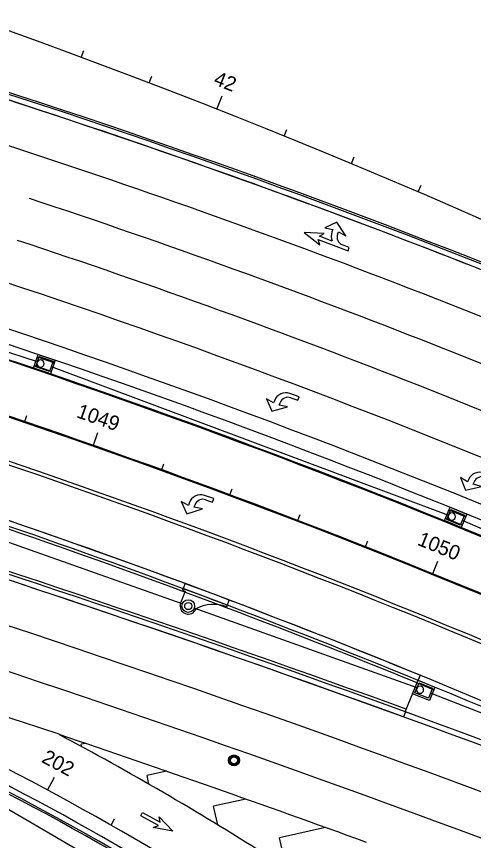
# Model space of a CAD drawing. Extents: x 468143 to 491361, y 1438528 to 1468730.
# Drawn here: x 487216.5 to 487342.4, y 1467246.7 to 1467474 of the extents above; entities that cross this region are included whole.
import ezdxf

# ---------------------------------------------------------------- set-up
doc = ezdxf.new("R2010")
doc.units = 0
doc.layers.add('Default', color=7, linetype='Continuous')
doc.layers.add('Xreference_dp', color=7, linetype='Continuous')

# ---------------------------------------------------------------- blocks, each defined once
blk = doc.blocks.new('POINT_DISPLAY')
at = {"layer": 'Default'}
blk.add_line((0, 0), (0, 0), dxfattribs=at)
blk = doc.blocks.new('InltCurb7_60')
at = {"layer": 'Default'}
for p, q in [((2.5, 4), (-2.5, 4)), ((-2.5, 4), (-2.5, 0)), ((2.5, 0), (2.5, 4)), ((-2.5, 0.75), (2.5, 0.75)), ((-2.5, 0), (2.5, 0))]:
    blk.add_line(p, q, dxfattribs=at)
blk.add_lwpolyline([(-2, 0.5), (2, 0.5), (2, 3.5), (-2, 3.5)], close=True, dxfattribs=at)
blk.add_circle((-1.04, 2.19), 1, dxfattribs=at)
for p in [(-2, 3.5), (0, 4), (0, 3.5), (0, 3.5), (2, 3.5), (-2, 2), (-2, 2), (-2, 0.5), (0, 2), (0, 2), (0, 0.5), (0, 0.5), (2, 2), (2, 2), (2, 0.5), (0, 0), (0, 0)]:
    blk.add_blockref('POINT_DISPLAY', p, dxfattribs=at)
blk = doc.blocks.new('InltCurb1_35')
at = {"layer": 'Default'}
for p, q in [((2.25, 2), (2.25, 5.5)), ((-10, 2), (-10, 0)), ((-10, 1.5), (3, 1.5)), ((3, 2), (2.25, 2)), ((3, 0), (3, 2))]:
    blk.add_line(p, q, dxfattribs=at)
for radius in [1.75, 1]:
    blk.add_circle((0, 5.5), radius, dxfattribs=at)
for centre, radius, start, end in [((0, 5.5), 2.25, 0, 180), ((-9.85, 12), 10, 269.1432, 319.4677)]:
    blk.add_arc(centre, radius, start, end, dxfattribs=at)
for p in [(-0.66, 7.12), (0, 7.75), (0, 7.25), (0, 7.25), (0.7, 7.1), (-1.75, 5.5), (-1.75, 5.5), (-1.62, 4.84), (-1.6, 6.2), (-1.22, 6.76), (0, 5.5), (0, 5.5), (1.26, 6.72), (1.6, 4.8), (1.62, 6.16), (1.75, 5.5), (1.75, 5.5), (-1.26, 4.28), (-0.7, 3.9), (0, 3.75), (0, 3.75), (0.66, 3.88), (1.22, 4.24), (0, 0), (0, 0)]:
    blk.add_blockref('POINT_DISPLAY', p, dxfattribs=at)
blk = doc.blocks.new('InltCurb7_40')
at = {"layer": 'Default'}
for p, q in [((2.5, 4), (-2.5, 4)), ((-2.5, 4), (-2.5, 0)), ((2.5, 3.25), (-2.5, 3.25)), ((2.5, 0), (2.5, 4)), ((-2.5, 0.75), (2.5, 0.75)), ((-2.5, 0), (2.5, 0))]:
    blk.add_line(p, q, dxfattribs=at)
blk.add_lwpolyline([(-2, 0.5), (2, 0.5), (2, 3.5), (-2, 3.5)], close=True, dxfattribs=at)
blk.add_circle((-1.04, 2.19), 1, dxfattribs=at)
for p in [(-2, 3.5), (0, 4), (0, 3.5), (0, 3.5), (2, 3.5), (-2, 2), (-2, 2), (-2, 0.5), (0, 2), (0, 2), (0, 0.5), (0, 0.5), (0, 0), (0, 0), (2, 2), (2, 2), (2, 0.5)]:
    blk.add_blockref('POINT_DISPLAY', p, dxfattribs=at)
blk = doc.blocks.new('MH2')
at = {"layer": 'Default'}
for p, q in [((-1.25, 0.03), (-1.05, 0.03)), ((-0.9, 0.87), (-0.76, 0.73)), ((-0.87, 0.9), (-0.73, 0.76)), ((-0.03, 1.25), (-0.03, 1.05)), ((0.03, 1.25), (0.03, 1.05)), ((0.87, 0.9), (0.73, 0.76)), ((0.9, 0.87), (0.76, 0.73)), ((1.05, 0.03), (1.25, 0.03)), ((-1.25, -0.03), (-1.05, -0.03)), ((-0.76, -0.73), (-0.9, -0.87)), ((-0.73, -0.76), (-0.87, -0.9)), ((-0.03, -1.05), (-0.03, -1.25)), ((0.03, -1.05), (0.03, -1.25)), ((0.73, -0.76), (0.87, -0.9)), ((0.76, -0.73), (0.9, -0.87)), ((1.05, -0.03), (1.25, -0.03))]:
    blk.add_line(p, q, dxfattribs=at)
for radius in [1.5, 1.25, 1.05, 1, 0.958]:
    blk.add_circle((0, 0), radius, dxfattribs=at)
for p in [(-1, 0), (-0.71, 0.71), (0, 1.5), (0, 1), (0, 0), (0, 0), (0, 0), (0.71, 0.71), (1, 0), (-0.71, -0.71), (0, -1), (0, -1.5), (0.71, -0.71)]:
    blk.add_blockref('POINT_DISPLAY', p, dxfattribs=at)
blk = doc.blocks.new('DALeftTurn_1')
at = {"layer": 'Default'}
for points in [[(5.67, 3.17), (2, 0.5), (4.33, 0.83), (4.33, 0.17)], [(6, 0.17), (6, 0.83), (8.25, 0.5), (5.67, 3.17)], [(2, -2.17), (0, -2.17), (0, -3.17), (2.67, -3.17)]]:
    blk.add_lwpolyline(points, dxfattribs=at)
for centre, radius in [((2, 0.17), 2.33), ((2.67, 0.17), 3.33)]:
    blk.add_arc(centre, radius, 270, 0, dxfattribs=at)
blk = doc.blocks.new('DARightThru')
at = {"layer": 'Default'}
for points in [[(5.05, 2.17), (8.83, 2.17), (7.83, 1), (13.08, 2.67), (7.83, 4.33), (8.83, 3.17), (0, 3.17), (0, 2.17), (2, 2.17)], [(4.33, -0.83), (2, -0.5), (5.67, -3.17), (8.25, -0.5), (6, -0.83), (6, -0.17)], [(4.33, -0.17), (4.33, -0.83)]]:
    blk.add_lwpolyline(points, dxfattribs=at)
for centre, radius, start, end in [((2, -0.17), 2.33, 360, 90), ((2.67, -0.17), 3.33, 0, 44.427)]:
    blk.add_arc(centre, radius, start, end, dxfattribs=at)
blk = doc.blocks.new('DAMerge_2')
at = {"layer": 'Default'}
blk.add_lwpolyline([(0.71, -4.09), (0, -3.39), (3.95, 0.56), (2.42, 0.68), (7.31, 3.21), (4.77, -1.68), (4.66, -0.15), (0.71, -4.09)], dxfattribs=at)
blk = doc.blocks.new('DALeftTurn_4_1')
at = {"layer": 'Default'}
for points in [[(5.67, 3.17), (2, 0.5), (4.33, 0.83), (4.33, 0.17)], [(6, 0.17), (6, 0.83), (8.25, 0.5), (5.67, 3.17)], [(2, -2.17), (0, -2.17), (0, -3.17), (2.67, -3.17)]]:
    blk.add_lwpolyline(points, dxfattribs=at)
for centre, radius in [((2, 0.17), 2.33), ((2.67, 0.17), 3.33)]:
    blk.add_arc(centre, radius, 270, 0, dxfattribs=at)
blk = doc.blocks.new('DAMerge_6')
at = {"layer": 'Default'}
blk.add_lwpolyline([(0.71, -4.09), (0, -3.39), (3.95, 0.56), (2.42, 0.68), (7.31, 3.21), (4.77, -1.68), (4.66, -0.15), (0.71, -4.09)], dxfattribs=at)
blk = doc.blocks.new('DALeftTurn_5')
at = {"layer": 'Default'}
for points in [[(5.67, 3.17), (2, 0.5), (4.33, 0.83), (4.33, 0.17)], [(6, 0.17), (6, 0.83), (8.25, 0.5), (5.67, 3.17)], [(2, -2.17), (0, -2.17), (0, -3.17), (2.67, -3.17)]]:
    blk.add_lwpolyline(points, dxfattribs=at)
for centre, radius in [((2, 0.17), 2.33), ((2.67, 0.17), 3.33)]:
    blk.add_arc(centre, radius, 270, 0, dxfattribs=at)

msp = doc.modelspace()

# ---------------------------------------------------------------- linework, layer by layer
at = {"layer": 'Xreference_dp'}
for p, q in [((487234.35, 1467462.72), (487235.05, 1467464.59)), ((487253.07, 1467455.67), (487253.78, 1467457.54)), ((487271.71, 1467448.43), (487273.18, 1467452.15)), ((487290.29, 1467441.01), (487291.04, 1467442.86)), ((487308.78, 1467433.4), (487309.55, 1467435.25)), ((487327.2, 1467425.61), (487327.99, 1467427.45)), ((487222.31, 1467378.76), (487152.2, 1467401.22)), ((487226.09, 1467377.47), (487335.55, 1467336.46)), ((487218.71, 1467362.02), (487219.36, 1467363.91)), ((487237.61, 1467355.48), (487238.94, 1467359.25)), ((487256.45, 1467348.76), (487257.13, 1467350.64)), ((487275.22, 1467341.86), (487275.92, 1467343.73)), ((487293.93, 1467334.78), (487294.64, 1467336.65)), ((487262.21, 1467312.03), (487195.84, 1467335.42)), ((487339.35, 1467335.08), (487425.86, 1467297.62)), ((487312.56, 1467327.52), (487313.3, 1467329.38)), ((487331.13, 1467320.09), (487332.64, 1467323.79)), ((487326.89, 1467288.88), (487265.49, 1467310.8)), ((487327.76, 1467292.3), (487327.19, 1467290.92)), ((487323.63, 1467282.25), (487327.19, 1467290.92)), ((487402.34, 1467259.43), (487330.59, 1467287.36)), ((487323.66, 1467282.24), (487323.15, 1467280.83)), ((487235.41, 1467273.54), (487234.34, 1467273.3)), ((487234.5, 1467272.62), (487234.34, 1467273.3)), ((487225.06, 1467260.66), (487226.96, 1467264.19)), ((487257.85, 1467265.83), (487252.48, 1467264.64)), ((487253.01, 1467262.28), (487252.48, 1467264.64)), ((487279.42, 1467217.41), (487205.88, 1467260.11)), ((487279.7, 1467258.18), (487270.82, 1467256.2)), ((487271.97, 1467251.04), (487270.82, 1467256.2)), ((487242.56, 1467250.98), (487243.55, 1467252.72)), ((487301.65, 1467250.33), (487289, 1467247.51)), ((487290.84, 1467239.2), (487289, 1467247.51))]:
    msp.add_line(p, q, dxfattribs=at)
for centre, radius, start, end in [((486537.7, 1465584.94), 2002.84, 65.37329, 99.90546), ((486541.29, 1465374.28), 2185, 65.36901, 75.94924), ((486541.29, 1465374.28), 2184.5, 65.36842, 75.94131), ((486541.29, 1465374.28), 2183, 65.36658, 75.94131), ((486541.29, 1465374.28), 2100, 65.36712, 99.90595), ((486541.29, 1465374.28), 2183, 66.41343, 72.14397), ((486541.29, 1465374.28), 2135, 66.02244, 75.79826), ((486541.29, 1465374.28), 2171, 68.95975, 72.15323), ((486541.29, 1465374.28), 2123, 65.38933, 75.79741), ((486541.29, 1465374.28), 2119, 65.36712, 75.79712), ((486541.29, 1465374.28), 2114.75, 65.36712, 75.79712), ((486541.29, 1465374.28), 2115, 65.17986, 75.79712), ((486541.29, 1465374.28), 2159, 65.36712, 71.6749), ((486541.29, 1465374.28), 2147, 65.36712, 71.66221), ((486541.29, 1465374.28), 2100.25, 66.83331, 75.79712), ((486541.29, 1465374.28), 2171, 65.37161, 68.95975), ((486541.29, 1465374.28), 2087.5, 66.11758, 75.79732), ((486541.29, 1465374.28), 2088.5, 66.11758, 75.79731), ((486541.29, 1465374.28), 2073, 67.70446, 74.37116), ((486541.29, 1465374.28), 2073, 65.16596, 74.37116), ((486541.29, 1465374.28), 2070.75, 67.70446, 74.37116), ((486541.29, 1465374.28), 2071.5, 67.70446, 74.37116), ((486023.86, 1463709.86), 3801.5, 70.00614, 72.73052), ((486023.86, 1463709.86), 3802.25, 70.00614, 72.73052), ((486023.86, 1463709.86), 3800, 70.00614, 72.73052), ((486023.86, 1463709.86), 3800, 66.68453, 72.73052), ((486837.51, 1466539.72), 818.51, 57.54696, 75.73928), ((486837.51, 1466539.72), 813.01, 57.54696, 75.73928), ((486837.51, 1466539.72), 814.51, 57.54696, 75.73928), ((486837.51, 1466539.72), 814.51, 57.54696, 75.73928), ((486837.51, 1466539.72), 812.51, 57.54696, 75.73928), ((486042.49, 1463704.02), 3763.7, 71.63582, 74.236), ((486023.86, 1463709.86), 3788, 66.09315, 72.73052), ((486023.86, 1463709.86), 3776, 66.11865, 72.73052), ((485288.17, 1462318.17), 5374.55, 66.0273, 67.70446), ((486236.65, 1464294.69), 3179.16, 66.0273, 70.00614), ((486023.86, 1463709.86), 3764, 69.97233, 71.33864), ((486837.51, 1466539.72), 833.51, 57.54696, 62.04513)]:
    msp.add_arc(centre, radius, start, end, dxfattribs=at)

# ---------------------------------------------------------------- block references
for name, p, rotation in [('DARightThru', (487308.99, 1467412.3), 159.18586267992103), ('DALeftTurn_1', (487293.27, 1467366.12), 159.7244670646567), ('DALeftTurn_4_1', (487346.67, 1467344.1), 157.38505044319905), ('DALeftTurn_5', (487346.67, 1467344.1), 157.38505044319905), ('DALeftTurn_1', (487269.83, 1467338.04), 161.30947600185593), ('InltCurb1_35', (487265.79, 1467316.56), 159.40571133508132), ('MH2', (487276.45, 1467268.83), 65.36711924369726), ('DAMerge_2', (487254.47, 1467255.41), -73.86292911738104), ('DAMerge_6', (487254.47, 1467255.41), -73.86292911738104)]:
    msp.add_blockref(name, p, dxfattribs=dict(at, rotation=rotation))
for name, p, yscale, rotation in [('InltCurb7_40', (487224.84, 1467380.01), -0.9999999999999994, -18.78519058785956), ('InltCurb7_40', (487338.28, 1467337.69), -0.9999999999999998, -22.604963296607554), ('InltCurb7_60', (487329.5, 1467289.97), -0.9999999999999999, -22.32581028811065)]:
    msp.add_blockref(name, p, dxfattribs=dict(at, yscale=yscale, rotation=rotation))

# ---------------------------------------------------------------- texts
for s, rotation, p in [('42', 338.501, (487270.57, 1467455.33)), ('1049', 340.6353, (487232.83, 1467363.52)), ('1050', 337.9069, (487326.73, 1467328.35)), ('202', 331.7393, (487223.16, 1467268.5))]:
    msp.add_text(s, height=4, rotation=rotation, dxfattribs=at).set_placement(p)

doc.saveas('drawing.dxf')
